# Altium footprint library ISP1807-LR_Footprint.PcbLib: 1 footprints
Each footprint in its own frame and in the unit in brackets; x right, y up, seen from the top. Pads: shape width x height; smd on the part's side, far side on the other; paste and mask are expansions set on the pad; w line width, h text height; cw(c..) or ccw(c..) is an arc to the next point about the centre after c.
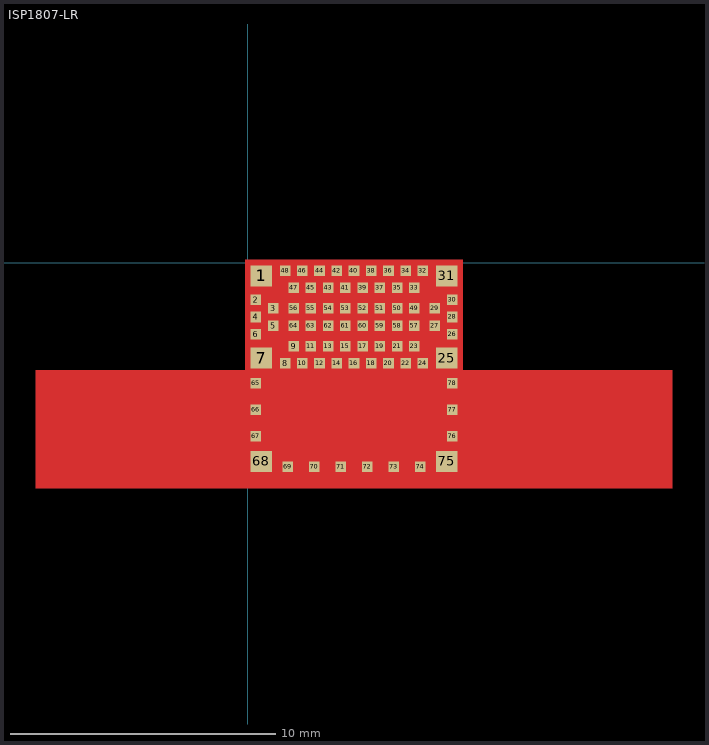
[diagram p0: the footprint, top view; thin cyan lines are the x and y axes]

## ISP1807-LR [mm] "Insight SiP BLE module all pins"
height 1
pads (78):
  rect 0.8x0.8 smd mask+0.05: 1(0.5,-0.5) 7(0.5,-3.6) 25(7.5,-3.6) 31(7.5,-0.5) 68(0.5,-7.5) 75(7.5,-7.5)
  rect 0.4x0.4 smd mask+0.05: 2(0.3,-1.4) 3(0.95,-1.725) 4(0.3,-2.05) 5(0.95,-2.375) 6(0.3,-2.7) 8(1.4,-3.8) 9(1.725,-3.15) 10(2.05,-3.8) 11(2.375,-3.15) 12(2.7,-3.8) 13(3.025,-3.15) 14(3.35,-3.8) 15(3.675,-3.15) 16(4,-3.8) 17(4.325,-3.15) 18(4.65,-3.8) 19(4.975,-3.15) 20(5.3,-3.8) 21(5.625,-3.15) 22(5.95,-3.8) 23(6.275,-3.15) 24(6.6,-3.8) 26(7.7,-2.7) 27(7.05,-2.375) 28(7.7,-2.05) 29(7.05,-1.725) 30(7.7,-1.4) 32(6.6,-0.3) 33(6.275,-0.95) 34(5.95,-0.3) 35(5.625,-0.95) 36(5.3,-0.3) 37(4.975,-0.95) 38(4.65,-0.3) 39(4.325,-0.95) 40(4,-0.3) 41(3.675,-0.95) 42(3.35,-0.3) 43(3.025,-0.95) 44(2.7,-0.3) 45(2.375,-0.95) 46(2.05,-0.3) 47(1.725,-0.95) 48(1.4,-0.3) 49(6.275,-1.725) 50(5.625,-1.725) 51(4.975,-1.725) 52(4.325,-1.725) 53(3.675,-1.725) 54(3.025,-1.725) 55(2.375,-1.725) 56(1.725,-1.725) 57(6.275,-2.375) 58(5.625,-2.375) 59(4.975,-2.375) 60(4.325,-2.375) 61(3.675,-2.375) 62(3.025,-2.375) 63(2.375,-2.375) 64(1.725,-2.375) 65(0.3,-4.55) 66(0.3,-5.55) 67(0.3,-6.55) 69(1.5,-7.701) 70(2.5,-7.701) 71(3.5,-7.701) 72(4.5,-7.701) 73(5.5,-7.701) 74(6.5,-7.701) 76(7.7,-6.55) 77(7.7,-5.55) 78(7.7,-4.55)
Top Layer:
  pour cut-out: 8.1,0.1 8.1,-4.05 16,-4.05 16,-8.5 -8,-8.5 -8,-4.05 -0.1,-4.05 -0.1,0.1
Mechanical 13:
  lines w0.1: 0,-8 0,0 8,0 8,-8 0,-8
Mechanical 15:
  lines w0.1: 3.5,-5.5 4.5,-5.5 ; 4,-6 4,-5
3D body: height 1.2, standoff 0.05, extent 0,-4.05 8,0.01
3D body: height 1.2, standoff 0.05, extent 0,-8 8,-4.05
